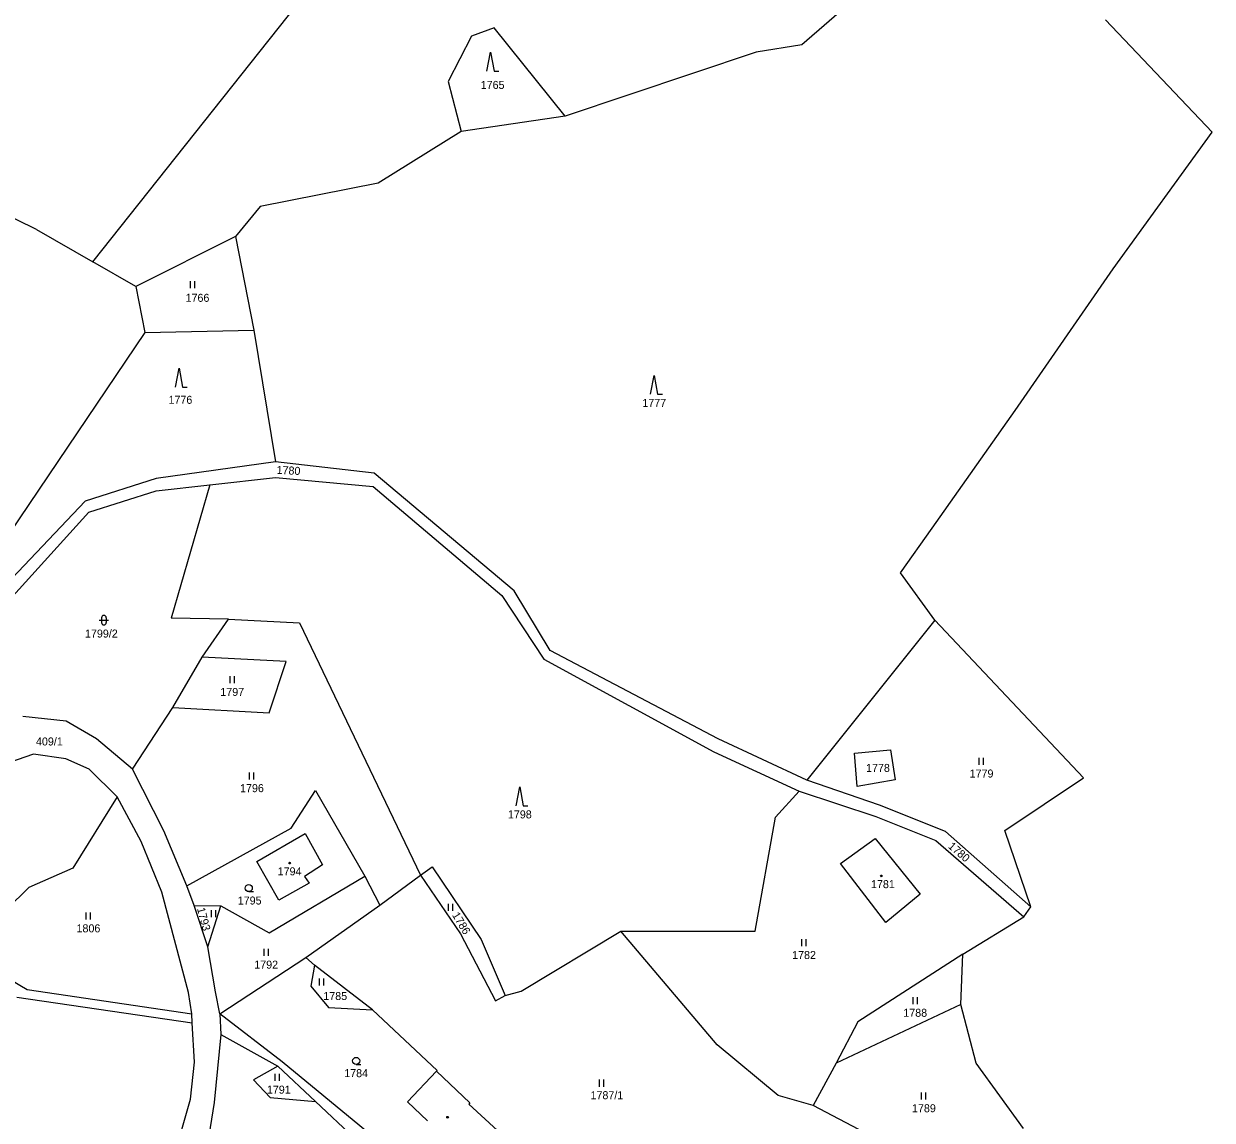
# Model space of a CAD drawing. Extents: x -670359 to -668019, y -978807 to -976674.
# Drawn here: x -668901.1 to -668648.7, y -978516 to -978283.1 of the extents above; entities that cross this region are included whole.
import ezdxf

# ---------------------------------------------------------------- set-up
doc = ezdxf.new("R2010")
doc.units = 0
for name, color, linetype in [('Hranice kat_území', 7, 'Continuous'), ('Hranice parcel', 7, 'Continuous'), ('Parcelní čísla', 7, 'Continuous'), ('Značky budov', 7, 'Continuous'), ('Značky kultur', 7, 'Continuous')]:
    doc.layers.add(name, color=color, linetype=linetype)

msp = doc.modelspace()

# ---------------------------------------------------------------- linework, layer by layer
at = {"layer": 'Hranice kat_území'}
for points in [[(-668648.66, -978306.11), (-668671.3, -978282.27)], [(-668669.69, -978335.14), (-668648.66, -978306.11)], [(-668690.49, -978365.26), (-668669.69, -978335.14)], [(-668708.14, -978390.22), (-668690.49, -978365.26)], [(-668714.87, -978399.73), (-668708.14, -978390.22)], [(-668707.6, -978409.78), (-668714.87, -978399.73)], [(-668676, -978443.29), (-668707.6, -978409.78)], [(-668692.69, -978454.44), (-668676, -978443.29)], [(-668687.2, -978470.62), (-668692.69, -978454.44)], [(-668688.68, -978472.75), (-668687.2, -978470.62)], [(-668701.62, -978480.68), (-668688.68, -978472.75)], [(-668702.05, -978491.39), (-668701.62, -978480.68)], [(-668698.82, -978503.85), (-668702.05, -978491.39)], [(-668688.74, -978517.71), (-668698.82, -978503.85)]]:
    msp.add_lwpolyline(points, dxfattribs=at)
at = {"layer": 'Hranice parcel'}
for points in [[(-668886.37, -978333.7), (-668801.69, -978226.94)], [(-668711.53, -978266.52), (-668735.82, -978287.61)], [(-668805.99, -978285.74), (-668810.96, -978295.41)], [(-668801.15, -978283.98), (-668805.99, -978285.74)], [(-668786.11, -978302.72), (-668801.15, -978283.98)], [(-668735.82, -978287.61), (-668745.53, -978289.12)], [(-668745.53, -978289.12), (-668786.11, -978302.72)], [(-668810.96, -978295.41), (-668808.18, -978306.01)], [(-668786.11, -978302.72), (-668808.18, -978306.01)], [(-668808.18, -978306.01), (-668825.82, -978316.98)], [(-668825.82, -978316.98), (-668850.87, -978321.9)], [(-668898.34, -978326.82), (-668910.96, -978320.68)], [(-668850.87, -978321.9), (-668856.11, -978328.29)], [(-668898.34, -978326.82), (-668886.37, -978333.7)], [(-668856.11, -978328.29), (-668877.28, -978338.92)], [(-668856.11, -978328.29), (-668852.21, -978348.2)], [(-668877.28, -978338.92), (-668886.37, -978333.7)], [(-668877.28, -978338.92), (-668875.35, -978348.67)], [(-668875.35, -978348.67), (-668908.29, -978397.36)], [(-668875.35, -978348.67), (-668852.21, -978348.2)], [(-668852.21, -978348.2), (-668847.57, -978376.12)], [(-668847.57, -978376.12), (-668872.92, -978379.67)], [(-668826.64, -978378.56), (-668847.57, -978376.12)], [(-668872.92, -978379.67), (-668888.06, -978384.52)], [(-668861.57, -978381.03), (-668847.63, -978379.47)], [(-668847.63, -978379.47), (-668826.85, -978381.36)], [(-668796.9, -978403.57), (-668826.64, -978378.56)], [(-668887.22, -978386.86), (-668872.97, -978382.31)], [(-668872.97, -978382.31), (-668861.57, -978381.03)], [(-668861.57, -978381.03), (-668869.76, -978409.32)], [(-668826.85, -978381.36), (-668799.56, -978404.56)], [(-668888.06, -978384.52), (-668920.5, -978418.67)], [(-668917.65, -978420.32), (-668887.22, -978386.86)], [(-668799.56, -978404.56), (-668790.59, -978418.08)], [(-668789.27, -978416.18), (-668796.9, -978403.57)], [(-668857.59, -978409.54), (-668869.76, -978409.32)], [(-668863.17, -978417.6), (-668857.59, -978409.54)], [(-668857.59, -978409.54), (-668842.48, -978410.36)], [(-668707.6, -978409.78), (-668734.76, -978443.78)], [(-668842.48, -978410.36), (-668816.83, -978463.93)], [(-668869.44, -978428.29), (-668863.17, -978417.6)], [(-668845.34, -978418.55), (-668863.17, -978417.6)], [(-668753.58, -978434.97), (-668789.27, -978416.18)], [(-668848.97, -978429.45), (-668845.34, -978418.55)], [(-668790.59, -978418.08), (-668754.51, -978437.75)], [(-668892.07, -978431.25), (-668901.25, -978430.21)], [(-668877.99, -978441.41), (-668869.44, -978428.29)], [(-668869.44, -978428.29), (-668848.97, -978429.45)], [(-668885.65, -978434.96), (-668892.07, -978431.25)], [(-668877.99, -978441.41), (-668885.65, -978434.96)], [(-668734.76, -978443.78), (-668753.58, -978434.97)], [(-668754.51, -978437.75), (-668736.4, -978446.07)], [(-668724.66, -978438.04), (-668716.96, -978437.29)], [(-668716.96, -978437.29), (-668716.03, -978443.71)], [(-668898.99, -978438.24), (-668907.61, -978441.21)], [(-668892.12, -978439.25), (-668898.99, -978438.24)], [(-668887.2, -978441.41), (-668892.12, -978439.25)], [(-668724.06, -978445.09), (-668724.66, -978438.04)], [(-668881.22, -978447.28), (-668887.2, -978441.41)], [(-668871.34, -978454.49), (-668877.99, -978441.41)], [(-668719.33, -978449.09), (-668734.76, -978443.78)], [(-668716.03, -978443.71), (-668724.06, -978445.09)], [(-668881.22, -978447.28), (-668890.68, -978462.47)], [(-668876.1, -978456.81), (-668881.22, -978447.28)], [(-668844.27, -978453.93), (-668839.09, -978445.94)], [(-668839.09, -978445.94), (-668828.6, -978464.12)], [(-668741.38, -978451.58), (-668736.4, -978446.07)], [(-668736.4, -978446.07), (-668720.09, -978451.48)], [(-668705.33, -978454.62), (-668719.33, -978449.09)], [(-668745.76, -978475.82), (-668741.38, -978451.58)], [(-668720.09, -978451.48), (-668707.37, -978456.58)], [(-668866.42, -978466.18), (-668871.34, -978454.49)], [(-668866.42, -978466.18), (-668844.27, -978453.93)], [(-668851.6, -978461), (-668841.33, -978455.1)], [(-668841.33, -978455.1), (-668837.6, -978461.72)], [(-668687.2, -978470.62), (-668705.33, -978454.62)], [(-668871.72, -978467.52), (-668876.1, -978456.81)], [(-668727.62, -978461.46), (-668720.25, -978456.11)], [(-668720.25, -978456.11), (-668710.69, -978467.96)], [(-668707.37, -978456.58), (-668688.68, -978472.75)], [(-668890.68, -978462.47), (-668899.96, -978466.55)], [(-668846.86, -978469.24), (-668851.6, -978461)], [(-668837.6, -978461.72), (-668841.41, -978464.22)], [(-668816.83, -978463.93), (-668814.35, -978462.15)], [(-668814.35, -978462.15), (-668803.94, -978477.6)], [(-668717.95, -978473.95), (-668727.62, -978461.46)], [(-668848.98, -978476.16), (-668828.6, -978464.12)], [(-668840.47, -978465.59), (-668846.86, -978469.24)], [(-668841.41, -978464.22), (-668840.47, -978465.59)], [(-668828.6, -978464.12), (-668825.43, -978470.26)], [(-668825.43, -978470.26), (-668816.83, -978463.93)], [(-668816.83, -978463.93), (-668808.32, -978476.4)], [(-668899.96, -978466.55), (-668913.96, -978480.22)], [(-668866.09, -978488.82), (-668871.72, -978467.52)], [(-668864.89, -978470.36), (-668866.42, -978466.18)], [(-668710.69, -978467.96), (-668717.95, -978473.95)], [(-668864.89, -978470.36), (-668859.21, -978470.46)], [(-668862, -978479.13), (-668864.89, -978470.36)], [(-668862, -978479.13), (-668859.21, -978470.46)], [(-668859.21, -978470.46), (-668848.98, -978476.16)], [(-668841.15, -978481.42), (-668825.43, -978470.26)], [(-668808.32, -978476.4), (-668800.88, -978490.61)], [(-668803.94, -978477.6), (-668798.86, -978489.45)], [(-668795.41, -978488.55), (-668774.25, -978475.8)], [(-668753.82, -978499.92), (-668774.25, -978475.8)], [(-668774.25, -978475.8), (-668745.76, -978475.82)], [(-668913.96, -978480.22), (-668900.33, -978488.22)], [(-668860.32, -978488.68), (-668862, -978479.13)], [(-668701.62, -978480.68), (-668723.96, -978495.09)], [(-668859.44, -978493.34), (-668841.15, -978481.42)], [(-668839.33, -978483.05), (-668841.15, -978481.42)], [(-668839.33, -978483.05), (-668840.13, -978487.52)], [(-668827.01, -978492.55), (-668839.33, -978483.05)], [(-668900.33, -978488.22), (-668865.37, -978493.39)], [(-668840.13, -978487.52), (-668836.37, -978492.06)], [(-668902.52, -978489.86), (-668865.32, -978495.31)], [(-668865.37, -978493.39), (-668866.09, -978488.82)], [(-668859.44, -978493.34), (-668860.32, -978488.68)], [(-668800.88, -978490.61), (-668798.86, -978489.45)], [(-668798.86, -978489.45), (-668795.41, -978488.55)], [(-668865.32, -978495.31), (-668865.37, -978493.39)], [(-668846.17, -978503.57), (-668859.44, -978493.34)], [(-668859.44, -978493.34), (-668859.2, -978497.74)], [(-668836.37, -978492.06), (-668827.01, -978492.55)], [(-668813.24, -978505.38), (-668827.01, -978492.55)], [(-668702.05, -978491.39), (-668728.52, -978503.88)], [(-668864.82, -978503.64), (-668865.32, -978495.31)], [(-668723.96, -978495.09), (-668728.52, -978503.88)], [(-668859.2, -978497.74), (-668860.65, -978512.19)], [(-668859.2, -978497.74), (-668847.1, -978504.5)], [(-668740.88, -978510.71), (-668753.82, -978499.92)], [(-668865.68, -978511.47), (-668864.82, -978503.64)], [(-668847.1, -978504.5), (-668852.24, -978507.38)], [(-668847.1, -978504.5), (-668839.1, -978512)], [(-668820.84, -978524.42), (-668846.17, -978503.57)], [(-668813.4, -978505.55), (-668819.55, -978512.04)], [(-668813.4, -978505.55), (-668813.24, -978505.38)], [(-668813.4, -978505.55), (-668806.32, -978512.28), (-668806.55, -978512.52)], [(-668728.52, -978503.88), (-668733.39, -978512.84)], [(-668852.24, -978507.38), (-668848.7, -978511.13)], [(-668733.39, -978512.84), (-668740.88, -978510.71)], [(-668869.69, -978525.63), (-668865.68, -978511.47)], [(-668860.65, -978512.19), (-668862.89, -978526.39)], [(-668848.7, -978511.13), (-668839.1, -978512)], [(-668839.1, -978512), (-668822.57, -978527.58)], [(-668819.55, -978512.04), (-668815.3, -978516.07)], [(-668800.48, -978518.18), (-668806.55, -978512.52)], [(-668722.37, -978518.63), (-668733.39, -978512.84)]]:
    msp.add_lwpolyline(points, dxfattribs=at)
at = {"layer": 'Značky budov'}
for centre in [(-668844.6, -978461.36), (-668718.95, -978464.08), (-668811.07, -978515.33)]:
    msp.add_circle(centre, 0.175, dxfattribs=at)
at = {"layer": 'Značky kultur'}
for p, q in [((-668865.71, -978337.8), (-668865.71, -978339.3)), ((-668864.71, -978339.3), (-668864.71, -978337.8)), ((-668885.06, -978409.77), (-668883.06, -978409.77)), ((-668884.56, -978409.27), (-668884.56, -978410.27)), ((-668883.56, -978409.27), (-668883.56, -978410.27)), ((-668857.32, -978421.67), (-668857.32, -978423.17)), ((-668856.32, -978423.17), (-668856.32, -978421.67)), ((-668698.22, -978438.99), (-668698.22, -978440.49)), ((-668697.22, -978440.49), (-668697.22, -978438.99)), ((-668853.17, -978442.1), (-668853.17, -978443.6)), ((-668852.17, -978443.6), (-668852.17, -978442.1)), ((-668853.28, -978467.42), (-668852.28, -978467.42)), ((-668810.92, -978469.98), (-668810.92, -978471.48)), ((-668809.92, -978471.48), (-668809.92, -978469.98)), ((-668887.9, -978471.87), (-668887.9, -978473.37)), ((-668886.9, -978473.37), (-668886.9, -978471.87)), ((-668861.27, -978471.37), (-668861.27, -978472.87)), ((-668860.27, -978472.87), (-668860.27, -978471.37)), ((-668735.88, -978477.53), (-668735.88, -978479.03)), ((-668734.88, -978479.03), (-668734.88, -978477.53)), ((-668850.11, -978479.57), (-668850.11, -978481.07)), ((-668849.11, -978481.07), (-668849.11, -978479.57)), ((-668838.36, -978485.88), (-668838.36, -978487.38)), ((-668837.36, -978487.38), (-668837.36, -978485.88)), ((-668712.27, -978489.8), (-668712.27, -978491.3)), ((-668711.27, -978491.3), (-668711.27, -978489.8)), ((-668830.47, -978504.12), (-668829.47, -978504.12)), ((-668847.75, -978506.12), (-668847.75, -978507.62)), ((-668846.75, -978507.62), (-668846.75, -978506.12)), ((-668778.89, -978507.34), (-668778.89, -978508.84)), ((-668777.89, -978508.84), (-668777.89, -978507.34)), ((-668710.46, -978510.07), (-668710.46, -978511.57)), ((-668709.46, -978511.57), (-668709.46, -978510.07))]:
    msp.add_line(p, q, dxfattribs=at)
for points in [[(-668802.69, -978293.16), (-668801.94, -978289.16), (-668801.19, -978293.16), (-668800.19, -978293.16)], [(-668868.84, -978360.28), (-668868.09, -978356.28), (-668867.34, -978360.28), (-668866.34, -978360.28)], [(-668767.94, -978361.79), (-668767.19, -978357.79), (-668766.44, -978361.79), (-668765.44, -978361.79)], [(-668796.49, -978449.17), (-668795.74, -978445.17), (-668794.99, -978449.17), (-668793.99, -978449.17)]]:
    msp.add_lwpolyline(points, dxfattribs=at)
for centre, radius in [((-668844.6, -978461.36), 0.175), ((-668718.95, -978464.08), 0.175), ((-668853.28, -978466.67), 0.75), ((-668830.47, -978503.37), 0.75), ((-668811.07, -978515.33), 0.175)]:
    msp.add_circle(centre, radius, dxfattribs=at)
for centre, start, end in [((-668884.06, -978409.27), 0, 180), ((-668884.06, -978410.27), 180, 0)]:
    msp.add_arc(centre, 0.5, start, end, dxfattribs=at)

# ---------------------------------------------------------------- texts
at = {"layer": 'Parcelní čísla'}
for s, p in [('1765', (-668804.02, -978296.96)), ('1766', (-668866.7, -978342.17)), ('1776', (-668870.33, -978363.83)), ('1777', (-668769.69, -978364.49)), ('1799/2', (-668888.06, -978413.47)), ('1797', (-668859.32, -978425.87)), ('409/1', (-668898.47, -978436.38)), ('1778', (-668722.18, -978442)), ('1779', (-668700.18, -978443.19)), ('1796', (-668855.13, -978446.3)), ('1798', (-668798.24, -978451.87)), ('1794', (-668847.14, -978463.96)), ('1781', (-668721.13, -978466.68)), ('1795', (-668855.62, -978470.16)), ('1806', (-668889.86, -978476.07)), ('1782', (-668737.88, -978481.73)), ('1792', (-668852.11, -978483.77)), ('1785', (-668837.45, -978490.44)), ('1788', (-668714.27, -978494)), ('1784', (-668833.01, -978506.82)), ('1791', (-668849.43, -978510.32)), ('1787/1', (-668780.7, -978511.5)), ('1789', (-668712.42, -978514.27))]:
    msp.add_text(s, height=1.7, dxfattribs=at).set_placement(p)
for s, rotation, p in [('1780', 356.8721, (-668847.41, -978378.68)), ('1780', 319.2289, (-668704.89, -978457.99)), ('1793', 284.8152, (-668864.29, -978471.01)), ('1786', 301.2392, (-668810.17, -978472.39))]:
    msp.add_text(s, height=1.7, rotation=rotation, dxfattribs=at).set_placement(p)

doc.saveas('drawing.dxf')
